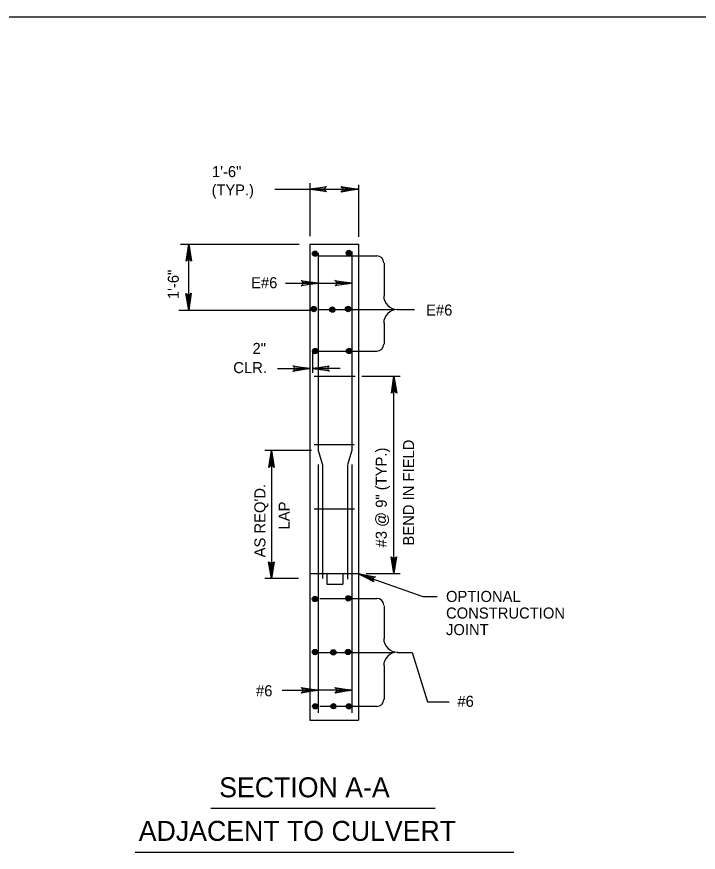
# Model space of a CAD drawing. Extents: x 639011 to 639866, y 298840 to 300028.
# Drawn here: x 639398.1 to 639582.6, y 299192.8 to 299418.8 of the extents above; entities that cross this region are included whole.
import ezdxf

# ---------------------------------------------------------------- set-up
doc = ezdxf.new("R2010")
doc.units = 0
doc.layers.add('2', color=7, linetype='Continuous')

msp = doc.modelspace()

# ---------------------------------------------------------------- linework, layer by layer
at = {"layer": '2'}
for p, q in [((639051.26, 299418.83), (639837.26, 299418.83)), ((639477.42, 299373.81), (639477.42, 299359.51)), ((639467.96, 299372.16), (639477.42, 299372.16)), ((639477.42, 299372.16), (639481.97, 299372.92)), ((639481.73, 299372.71), (639477.42, 299372.16)), ((639477.42, 299372.16), (639481.58, 299372.39)), ((639477.42, 299372.16), (639481.58, 299372.18)), ((639477.42, 299372.16), (639490.46, 299372.16)), ((639481.58, 299371.96), (639477.42, 299372.16)), ((639477.42, 299372.16), (639481.75, 299371.64)), ((639481.98, 299371.45), (639477.42, 299372.16)), ((639481.58, 299372.39), (639481.73, 299372.71)), ((639481.58, 299371.96), (639481.58, 299372.39)), ((639481.75, 299371.64), (639481.58, 299371.96)), ((639481.97, 299372.92), (639481.73, 299372.71)), ((639481.75, 299371.64), (639481.98, 299371.45)), ((639486.13, 299372.67), (639485.9, 299372.87)), ((639485.9, 299372.87), (639490.46, 299372.16)), ((639490.46, 299372.16), (639485.91, 299371.4)), ((639485.91, 299371.4), (639486.15, 299371.61)), ((639486.13, 299372.67), (639486.3, 299372.36)), ((639490.46, 299372.16), (639486.13, 299372.67)), ((639486.15, 299371.61), (639490.46, 299372.16)), ((639486.3, 299371.92), (639486.15, 299371.61)), ((639486.3, 299372.36), (639490.46, 299372.16)), ((639486.3, 299372.36), (639486.3, 299371.92)), ((639490.46, 299372.16), (639486.3, 299371.92)), ((639490.46, 299372.16), (639486.3, 299372.14)), ((639490.61, 299373.36), (639490.61, 299359.34)), ((639442.43, 299357.31), (639474.54, 299357.31)), ((639443.97, 299352.75), (639444.68, 299357.31)), ((639444.68, 299357.31), (639444.16, 299352.98)), ((639444.48, 299353.14), (639444.68, 299357.31)), ((639444.68, 299339.46), (639444.68, 299357.31)), ((639444.68, 299357.31), (639444.91, 299353.14)), ((639445.22, 299352.99), (639444.68, 299357.31)), ((639444.68, 299357.31), (639445.44, 299352.75)), ((639444.68, 299357.31), (639444.69, 299353.14)), ((639477.42, 299357.31), (639490.61, 299357.31)), ((639477.42, 299357.31), (639477.42, 299261.31)), ((639490.61, 299357.31), (639490.61, 299228.61)), ((639479.67, 299354.76), (639479.67, 299301.51)), ((639479.82, 299354.16), (639495.57, 299354.16)), ((639488.82, 299355.36), (639488.82, 299301.51)), ((639444.16, 299352.98), (639443.97, 299352.75)), ((639444.16, 299352.98), (639444.48, 299353.14)), ((639444.48, 299353.14), (639444.91, 299353.14)), ((639444.91, 299353.14), (639445.22, 299352.99)), ((639445.44, 299352.75), (639445.22, 299352.99)), ((639497.52, 299352.21), (639497.52, 299343.36)), ((639470.9, 299346.81), (639479.67, 299346.81)), ((639475.33, 299347.32), (639475.1, 299347.52)), ((639475.1, 299347.52), (639479.67, 299346.81)), ((639479.67, 299346.81), (639475.11, 299346.05)), ((639475.33, 299347.32), (639475.5, 299347.01)), ((639479.67, 299346.81), (639475.33, 299347.32)), ((639475.35, 299346.26), (639479.67, 299346.81)), ((639475.5, 299347.01), (639479.67, 299346.81)), ((639475.5, 299347.01), (639475.5, 299346.57)), ((639479.67, 299346.81), (639475.5, 299346.57)), ((639479.67, 299346.81), (639475.5, 299346.79)), ((639479.67, 299346.81), (639488.82, 299346.81)), ((639484.48, 299347.32), (639484.25, 299347.52)), ((639484.25, 299347.52), (639488.82, 299346.81)), ((639488.82, 299346.81), (639484.26, 299346.05)), ((639484.48, 299347.32), (639484.65, 299347.01)), ((639488.82, 299346.81), (639484.48, 299347.32)), ((639484.5, 299346.26), (639488.82, 299346.81)), ((639484.65, 299347.01), (639488.82, 299346.81)), ((639484.65, 299347.01), (639484.65, 299346.57)), ((639488.82, 299346.81), (639484.65, 299346.57)), ((639488.82, 299346.81), (639484.65, 299346.79)), ((639475.11, 299346.05), (639475.35, 299346.26)), ((639475.5, 299346.57), (639475.35, 299346.26)), ((639484.26, 299346.05), (639484.5, 299346.26)), ((639484.65, 299346.57), (639484.5, 299346.26)), ((639444.68, 299339.46), (639443.91, 299344.01)), ((639443.91, 299344.01), (639444.13, 299343.78)), ((639444.44, 299343.62), (639444.13, 299343.78)), ((639444.13, 299343.78), (639444.68, 299339.46)), ((639444.87, 299343.63), (639444.44, 299343.62)), ((639444.68, 299339.46), (639444.44, 299343.62)), ((639444.68, 299339.46), (639444.66, 299343.62)), ((639445.38, 299344.02), (639444.68, 299339.46)), ((639444.68, 299339.46), (639445.19, 299343.79)), ((639444.87, 299343.63), (639444.68, 299339.46)), ((639445.19, 299343.79), (639444.87, 299343.63)), ((639445.19, 299343.79), (639445.38, 299344.02)), ((639441.98, 299339.46), (639477.71, 299339.46)), ((639479.96, 299339.61), (639500.07, 299339.61)), ((639501.11, 299339.61), (639505.73, 299339.61)), ((639497.52, 299336.01), (639497.52, 299330.31)), ((639497.52, 299336.01), (639497.52, 299330.31)), ((639477.42, 299330.31), (639477.42, 299325.66)), ((639478.17, 299328.36), (639478.17, 299322.54)), ((639479.67, 299328.36), (639495.57, 299328.36)), ((639473.08, 299324.19), (639472.85, 299324.38)), ((639472.85, 299324.38), (639477.42, 299323.67)), ((639473.08, 299324.19), (639473.25, 299323.87)), ((639477.42, 299323.67), (639473.08, 299324.19)), ((639478.17, 299323.67), (639482.72, 299324.43)), ((639482.48, 299324.22), (639478.17, 299323.67)), ((639482.33, 299323.9), (639482.48, 299324.22)), ((639482.72, 299324.43), (639482.48, 299324.22)), ((639468.71, 299323.67), (639477.42, 299323.67)), ((639477.42, 299323.67), (639472.86, 299322.91)), ((639472.86, 299322.91), (639473.1, 299323.12)), ((639473.1, 299323.12), (639477.42, 299323.67)), ((639473.25, 299323.43), (639473.1, 299323.12)), ((639473.25, 299323.87), (639477.42, 299323.67)), ((639473.25, 299323.87), (639473.25, 299323.43)), ((639477.42, 299323.67), (639473.25, 299323.43)), ((639477.42, 299323.67), (639473.25, 299323.65)), ((639478.17, 299323.67), (639482.33, 299323.9)), ((639478.17, 299323.67), (639482.33, 299323.69)), ((639485.65, 299323.67), (639478.17, 299323.67)), ((639482.33, 299323.47), (639478.17, 299323.67)), ((639478.17, 299323.67), (639482.5, 299323.15)), ((639482.73, 299322.96), (639478.17, 299323.67)), ((639482.33, 299323.47), (639482.33, 299323.9)), ((639482.5, 299323.15), (639482.33, 299323.47)), ((639482.5, 299323.15), (639482.73, 299322.96)), ((639478.61, 299321.61), (639489.71, 299321.61)), ((639491.52, 299321.61), (639501.86, 299321.61)), ((639499.51, 299317.05), (639500.21, 299321.61)), ((639499.51, 299317.05), (639500.21, 299321.61)), ((639500.21, 299321.61), (639499.7, 299317.28)), ((639500.21, 299321.61), (639499.7, 299317.28)), ((639500.02, 299317.44), (639500.21, 299321.61)), ((639500.02, 299317.44), (639500.21, 299321.61)), ((639500.21, 299268.21), (639500.21, 299321.61)), ((639500.21, 299321.61), (639500.45, 299317.44)), ((639500.76, 299317.29), (639500.21, 299321.61)), ((639500.21, 299321.61), (639500.98, 299317.05)), ((639500.21, 299321.61), (639500.23, 299317.44)), ((639500.21, 299321.61), (639500.45, 299317.44)), ((639500.76, 299317.29), (639500.21, 299321.61)), ((639500.21, 299321.61), (639500.98, 299317.05)), ((639500.21, 299321.61), (639500.23, 299317.44)), ((639499.7, 299317.28), (639500.02, 299317.44)), ((639499.7, 299317.28), (639500.02, 299317.44)), ((639500.02, 299317.44), (639500.45, 299317.44)), ((639500.02, 299317.44), (639500.45, 299317.44)), ((639500.45, 299317.44), (639500.76, 299317.29)), ((639500.45, 299317.44), (639500.76, 299317.29)), ((639499.7, 299317.28), (639499.51, 299317.05)), ((639499.7, 299317.28), (639499.51, 299317.05)), ((639500.98, 299317.05), (639500.76, 299317.29)), ((639500.98, 299317.05), (639500.76, 299317.29)), ((639477.86, 299301.51), (639465.27, 299301.51)), ((639466.36, 299296.95), (639467.07, 299301.51)), ((639467.07, 299301.51), (639466.55, 299297.18)), ((639466.87, 299297.34), (639467.07, 299301.51)), ((639467.07, 299301.51), (639467.07, 299266.86)), ((639467.07, 299301.51), (639467.3, 299297.34)), ((639467.61, 299297.19), (639467.07, 299301.51)), ((639467.07, 299301.51), (639467.83, 299296.95)), ((639467.07, 299301.51), (639467.08, 299297.34)), ((639478.61, 299303.16), (639489.42, 299303.16)), ((639479.67, 299301.51), (639480.87, 299297.6)), ((639488.82, 299301.51), (639487.6, 299297.63)), ((639466.55, 299297.18), (639466.36, 299296.95)), ((639466.55, 299297.18), (639466.87, 299297.34)), ((639466.87, 299297.34), (639467.3, 299297.34)), ((639467.3, 299297.34), (639467.61, 299297.19)), ((639467.83, 299296.95), (639467.61, 299297.19)), ((639479.67, 299297.77), (639479.67, 299230.56)), ((639480.86, 299297.77), (639480.86, 299266.87)), ((639487.61, 299297.57), (639487.61, 299266.71)), ((639488.82, 299297.77), (639488.82, 299230.56)), ((639478.61, 299285.76), (639489.57, 299285.76)), ((639478.61, 299285.76), (639489.57, 299285.76)), ((639500.21, 299268.21), (639499.45, 299272.76)), ((639499.45, 299272.76), (639499.67, 299272.53)), ((639499.98, 299272.37), (639499.67, 299272.53)), ((639499.67, 299272.53), (639500.21, 299268.21)), ((639500.41, 299272.38), (639499.98, 299272.37)), ((639500.21, 299268.21), (639499.98, 299272.37)), ((639500.21, 299268.21), (639500.2, 299272.37)), ((639500.92, 299272.77), (639500.21, 299268.21)), ((639500.21, 299268.21), (639500.73, 299272.54)), ((639500.41, 299272.38), (639500.21, 299268.21)), ((639500.73, 299272.54), (639500.41, 299272.38)), ((639500.73, 299272.54), (639500.92, 299272.77)), ((639467.07, 299266.86), (639466.3, 299271.41)), ((639466.3, 299271.41), (639466.52, 299271.18)), ((639466.83, 299271.02), (639466.52, 299271.18)), ((639466.52, 299271.18), (639467.07, 299266.86)), ((639467.26, 299271.03), (639466.83, 299271.02)), ((639467.07, 299266.86), (639466.83, 299271.02)), ((639467.07, 299266.86), (639467.05, 299271.02)), ((639467.77, 299271.42), (639467.07, 299266.86)), ((639467.07, 299266.86), (639467.58, 299271.19)), ((639467.26, 299271.03), (639467.07, 299266.86)), ((639467.58, 299271.19), (639467.26, 299271.03)), ((639467.58, 299271.19), (639467.77, 299271.42)), ((639477.42, 299268.21), (639482.07, 299268.21)), ((639477.42, 299268.21), (639482.07, 299268.21)), ((639478.61, 299268.21), (639489.57, 299268.21)), ((639478.61, 299268.21), (639489.57, 299268.21)), ((639482.07, 299268.21), (639482.07, 299265.36)), ((639482.07, 299268.21), (639482.07, 299265.36)), ((639486.42, 299268.21), (639486.42, 299265.36)), ((639486.42, 299268.21), (639490.61, 299268.21)), ((639486.42, 299268.21), (639486.42, 299265.36)), ((639486.42, 299268.21), (639490.61, 299268.21)), ((639494.51, 299266.6), (639490.64, 299268.15)), ((639490.64, 299268.15), (639494.57, 299266.24)), ((639494.72, 299265.99), (639490.64, 299268.15)), ((639490.64, 299268.15), (639494.65, 299267.01)), ((639494.9, 299267.26), (639490.64, 299268.15)), ((639490.64, 299268.15), (639495.19, 299267.38)), ((639490.64, 299268.15), (639494.58, 299266.8)), ((639490.64, 299268.15), (639508.05, 299262.06)), ((639492.73, 299268.21), (639501.86, 299268.21)), ((639474.38, 299266.86), (639465.27, 299266.86)), ((639482.07, 299265.36), (639486.42, 299265.36)), ((639482.07, 299265.36), (639486.42, 299265.36)), ((639494.51, 299266.6), (639494.65, 299267.01)), ((639494.57, 299266.24), (639494.51, 299266.6)), ((639494.57, 299266.24), (639494.72, 299265.99)), ((639494.65, 299267.01), (639494.9, 299267.26)), ((639495.19, 299267.38), (639494.9, 299267.26)), ((639477.42, 299263.11), (639477.42, 299228.61)), ((639477.42, 299263.11), (639477.42, 299228.61)), ((639480.11, 299261.46), (639495.57, 299261.46)), ((639488.82, 299262.21), (639488.82, 299230.86)), ((639508.05, 299262.06), (639511.9, 299262.06)), ((639497.52, 299259.51), (639497.52, 299250.66)), ((639479.96, 299246.91), (639499.92, 299246.91)), ((639479.96, 299246.91), (639499.92, 299246.91)), ((639501.11, 299246.91), (639505.17, 299246.91)), ((639505.17, 299246.91), (639509.25, 299233.55)), ((639497.52, 299243.31), (639497.52, 299234.16)), ((639497.52, 299243.31), (639497.52, 299234.16)), ((639469.98, 299236.67), (639479.67, 299236.67)), ((639475.33, 299237.18), (639475.1, 299237.38)), ((639475.1, 299237.38), (639479.67, 299236.67)), ((639479.67, 299236.67), (639475.11, 299235.91)), ((639475.11, 299235.91), (639475.35, 299236.12)), ((639475.33, 299237.18), (639475.5, 299236.87)), ((639479.67, 299236.67), (639475.33, 299237.18)), ((639475.35, 299236.12), (639479.67, 299236.67)), ((639475.5, 299236.43), (639475.35, 299236.12)), ((639475.5, 299236.87), (639479.67, 299236.67)), ((639475.5, 299236.87), (639475.5, 299236.43)), ((639479.67, 299236.67), (639475.5, 299236.43)), ((639479.67, 299236.67), (639475.5, 299236.65)), ((639488.82, 299236.67), (639479.67, 299236.67)), ((639484.48, 299237.18), (639484.25, 299237.38)), ((639484.25, 299237.38), (639488.82, 299236.67)), ((639488.82, 299236.67), (639484.26, 299235.91)), ((639484.26, 299235.91), (639484.5, 299236.12)), ((639484.48, 299237.18), (639484.65, 299236.87)), ((639488.82, 299236.67), (639484.48, 299237.18)), ((639484.5, 299236.12), (639488.82, 299236.67)), ((639484.65, 299236.43), (639484.5, 299236.12)), ((639484.65, 299236.87), (639488.82, 299236.67)), ((639484.65, 299236.87), (639484.65, 299236.43)), ((639488.82, 299236.67), (639484.65, 299236.43)), ((639488.82, 299236.67), (639484.65, 299236.65)), ((639480.11, 299232.36), (639495.57, 299232.36)), ((639480.11, 299232.36), (639495.57, 299232.36)), ((639509.25, 299233.55), (639515.16, 299233.55)), ((639477.42, 299228.61), (639490.61, 299228.61)), ((639477.42, 299228.61), (639490.61, 299228.61)), ((639450.64, 299204.81), (639511.36, 299204.81)), ((639430.21, 299192.85), (639532.66, 299192.85))]:
    msp.add_line(p, q, dxfattribs=at)
for centre, radius in [((639478.87, 299354.75), 0.715), ((639478.87, 299354.75), 0.511), ((639478.87, 299354.75), 0.511), ((639478.87, 299354.75), 0.279), ((639478.87, 299354.75), 0.279), ((639478.87, 299354.75), 0.141), ((639478.87, 299354.75), 0.141), ((639478.87, 299354.75), 0.0604), ((639478.87, 299354.75), 0.0604), ((639488, 299354.94), 0.715), ((639488, 299354.94), 0.511), ((639488, 299354.94), 0.511), ((639488, 299354.94), 0.279), ((639488, 299354.94), 0.279), ((639488, 299354.94), 0.141), ((639488, 299354.94), 0.141), ((639488, 299354.94), 0.0604), ((639488, 299354.94), 0.0604), ((639478.54, 299339.76), 0.715), ((639478.54, 299339.76), 0.715), ((639478.54, 299339.76), 0.511), ((639478.54, 299339.76), 0.511), ((639478.54, 299339.76), 0.279), ((639478.54, 299339.76), 0.279), ((639478.54, 299339.76), 0.141), ((639478.54, 299339.76), 0.141), ((639483.55, 299339.62), 0.715), ((639483.55, 299339.62), 0.511), ((639483.55, 299339.62), 0.511), ((639483.55, 299339.62), 0.279), ((639483.55, 299339.62), 0.279), ((639487.8, 299339.76), 0.715), ((639487.8, 299339.76), 0.715), ((639487.8, 299339.76), 0.511), ((639487.8, 299339.76), 0.511), ((639487.8, 299339.76), 0.279), ((639487.8, 299339.76), 0.279), ((639487.8, 299339.76), 0.141), ((639487.8, 299339.76), 0.141), ((639478.54, 299339.76), 0.0604), ((639478.54, 299339.76), 0.0604), ((639483.55, 299339.62), 0.141), ((639483.55, 299339.62), 0.141), ((639483.55, 299339.62), 0.0604), ((639483.55, 299339.62), 0.0604), ((639487.8, 299339.76), 0.0604), ((639487.8, 299339.76), 0.0604), ((639478.92, 299328.41), 0.715), ((639478.92, 299328.41), 0.715), ((639478.92, 299328.41), 0.511), ((639478.92, 299328.41), 0.511), ((639478.92, 299328.41), 0.279), ((639478.92, 299328.41), 0.279), ((639488.06, 299328.43), 0.715), ((639488.06, 299328.43), 0.715), ((639488.06, 299328.43), 0.511), ((639488.06, 299328.43), 0.511), ((639488.06, 299328.43), 0.279), ((639488.06, 299328.43), 0.279), ((639478.92, 299328.41), 0.141), ((639478.92, 299328.41), 0.141), ((639478.92, 299328.41), 0.0604), ((639478.92, 299328.41), 0.0604), ((639488.06, 299328.43), 0.141), ((639488.06, 299328.43), 0.141), ((639488.06, 299328.43), 0.0604), ((639488.06, 299328.43), 0.0604), ((639478.82, 299261.36), 0.715), ((639478.82, 299261.36), 0.715), ((639478.82, 299261.36), 0.511), ((639478.82, 299261.36), 0.511), ((639478.82, 299261.36), 0.279), ((639478.82, 299261.36), 0.279), ((639478.82, 299261.36), 0.141), ((639478.82, 299261.36), 0.141), ((639478.82, 299261.36), 0.0604), ((639478.82, 299261.36), 0.0604), ((639487.84, 299261.52), 0.715), ((639487.84, 299261.52), 0.715), ((639487.84, 299261.52), 0.511), ((639487.84, 299261.52), 0.511), ((639487.84, 299261.52), 0.279), ((639487.84, 299261.52), 0.279), ((639487.84, 299261.52), 0.141), ((639487.84, 299261.52), 0.141), ((639487.84, 299261.52), 0.0604), ((639487.84, 299261.52), 0.0604), ((639478.85, 299247.01), 0.715), ((639478.85, 299247.01), 0.715), ((639478.85, 299247.01), 0.511), ((639478.85, 299247.01), 0.511), ((639478.85, 299247.01), 0.279), ((639478.85, 299247.01), 0.279), ((639483.8, 299246.93), 0.715), ((639483.8, 299246.93), 0.715), ((639483.8, 299246.93), 0.511), ((639483.8, 299246.93), 0.511), ((639487.77, 299247.02), 0.715), ((639487.77, 299247.02), 0.715), ((639487.77, 299247.02), 0.511), ((639487.77, 299247.02), 0.511), ((639487.77, 299247.02), 0.279), ((639487.77, 299247.02), 0.279), ((639478.85, 299247.01), 0.141), ((639478.85, 299247.01), 0.141), ((639478.85, 299247.01), 0.0604), ((639478.85, 299247.01), 0.0604), ((639483.8, 299246.93), 0.279), ((639483.8, 299246.93), 0.279), ((639483.8, 299246.93), 0.141), ((639483.8, 299246.93), 0.141), ((639483.8, 299246.93), 0.0604), ((639483.8, 299246.93), 0.0604), ((639487.77, 299247.02), 0.141), ((639487.77, 299247.02), 0.141), ((639487.77, 299247.02), 0.0604), ((639487.77, 299247.02), 0.0604), ((639478.92, 299232.32), 0.715), ((639478.92, 299232.32), 0.715), ((639478.92, 299232.32), 0.511), ((639478.92, 299232.32), 0.511), ((639478.92, 299232.32), 0.279), ((639478.92, 299232.32), 0.279), ((639478.92, 299232.32), 0.141), ((639478.92, 299232.32), 0.141), ((639478.92, 299232.32), 0.0604), ((639478.92, 299232.32), 0.0604), ((639483.84, 299232.35), 0.715), ((639483.84, 299232.35), 0.715), ((639483.84, 299232.35), 0.511), ((639483.84, 299232.35), 0.511), ((639483.84, 299232.35), 0.279), ((639483.84, 299232.35), 0.279), ((639483.84, 299232.35), 0.141), ((639483.84, 299232.35), 0.141), ((639483.84, 299232.35), 0.0604), ((639483.84, 299232.35), 0.0604), ((639488.01, 299232.3), 0.715), ((639488.01, 299232.3), 0.715), ((639488.01, 299232.3), 0.511), ((639488.01, 299232.3), 0.511), ((639488.01, 299232.3), 0.279), ((639488.01, 299232.3), 0.279), ((639488.01, 299232.3), 0.141), ((639488.01, 299232.3), 0.141), ((639488.01, 299232.3), 0.0604), ((639488.01, 299232.3), 0.0604)]:
    msp.add_circle(centre, radius, dxfattribs=at)
for centre, radius, start, end in [((639495.58, 299352.27), 1.86, 0, 90), ((639501.15, 299343.36), 3.71, 180, 270), ((639501.15, 299335.94), 3.71, 90, 180), ((639495.58, 299330.27), 1.86, 270, 0), ((639495.58, 299259.65), 1.86, 0, 90), ((639501.15, 299250.69), 3.71, 180, 270), ((639501.15, 299243.26), 3.71, 90, 180), ((639501.15, 299243.26), 3.71, 90, 180), ((639495.58, 299234.17), 1.86, 270, 0), ((639495.58, 299234.17), 1.86, 270, 0)]:
    msp.add_arc(centre, radius, start, end, dxfattribs=at)

# ---------------------------------------------------------------- texts
for s, height, p in [('1\'-6"', 2.988, (639450.97, 299375.44)), ('(TYP.)', 2.958, (639450.89, 299370.51)), ('E#6', 2.988, (639461.55, 299345.4)), ('E#6', 2.988, (639508.9, 299338.01)), ('2"', 2.988, (639461.94, 299327.63)), ('CLR.', 2.988, (639456.74, 299322.44)), ('OPTIONAL', 2.988, (639514.3, 299260.55)), ('CONSTRUCTION', 2.988, (639514.3, 299256.06)), ('JOINT', 2.988, (639514.3, 299251.58)), ('#6', 2.988, (639462.9, 299235.04)), ('#6', 2.988, (639517.38, 299232.19)), ('SECTION A-A', 5.4, (639452.92, 299207.72)), ('ADJACENT TO CULVERT', 5.4, (639431.16, 299195.94))]:
    msp.add_text(s, height=height, dxfattribs=at).set_placement(p)
for s, p in [('1\'-6"', (639442, 299342.45)), ('BEND IN FIELD', (639505.65, 299275.81)), ('#3 @ 9" (TYP.)', (639498.26, 299275.29)), ("AS REQ'D.", (639465.43, 299272.62)), ('LAP', (639472, 299280.16))]:
    msp.add_text(s, height=2.988, rotation=90, dxfattribs=at).set_placement(p)

doc.saveas('drawing.dxf')
